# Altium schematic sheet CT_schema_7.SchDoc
size 278 x 170 mm
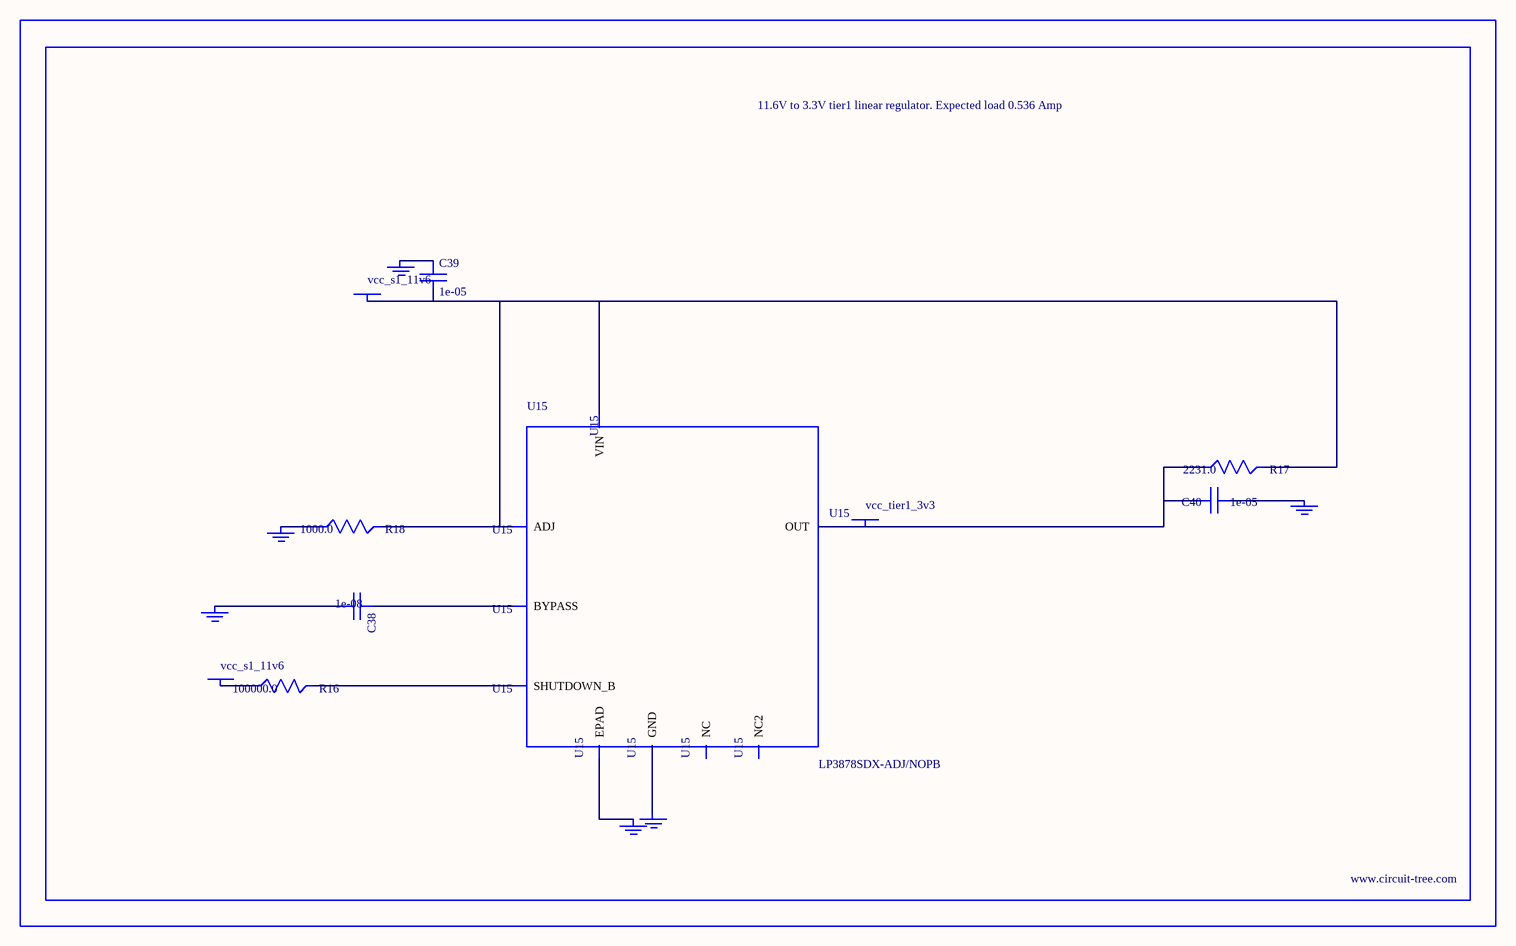
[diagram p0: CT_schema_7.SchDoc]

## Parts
BORDER6  (no value)
C38  1e-08  [C0402]
C39  1e-05  [C1210]
C40  1e-05  [C1210]
GND_INSTANCE_6_0  (no value)
GND_INSTANCE_6_1  (no value)
GND_INSTANCE_6_2  (no value)
GND_INSTANCE_6_3  (no value)
GND_INSTANCE_6_4  (no value)
GND_INSTANCE_6_5  (no value)
POWER_INSTANCE_6_0  vcc_s1_11v6
POWER_INSTANCE_6_1  vcc_s1_11v6
POWER_INSTANCE_6_2  vcc_tier1_3v3
R16  100000.0  [R0603]
R17  2231.0  [R0603]
R18  1000.0  [R0603]
U15  LP3878SDX-ADJ/NOPB  [WSON-8]

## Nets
NetC38_1: C38.1 U15.1(BYPASS)
NetC38_2: C38.2 GND_INSTANCE_6_0.0(GND)
NetC39_1: C39.1 GND_INSTANCE_6_1.0(GND)
NetC39_2: C39.2 POWER_INSTANCE_6_0.0(PWR) R17.2 R18.2 U15.4(VIN) U15.6(ADJ)
NetC40_1: C40.1 GND_INSTANCE_6_2.0(GND)
NetC40_2: C40.2 POWER_INSTANCE_6_2.0(PWR) R17.1 U15.5(OUT)
NetGND_INSTANCE_6_3_0: GND_INSTANCE_6_3.0(GND) R18.1
NetGND_INSTANCE_6_4_0: GND_INSTANCE_6_4.0(GND) U15.PAD(EPAD)
NetGND_INSTANCE_6_5_0: GND_INSTANCE_6_5.0(GND) U15.3(GND)
NetPOWER_INSTANCE_6_1_0: POWER_INSTANCE_6_1.0(PWR) R16.1
NetR16_2: R16.2 U15.8(SHUTDOWN_B)

Not connected (* = marked no-connect by the designer): U15 2(NC) 7(NC2)

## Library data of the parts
BORDER6 = BORDER_PAGE6
C38 = C0402C103K3RAC
C39 = C1210C106K5PACTU
C40 = GRM32DR61E106MA12L
GND_INSTANCE_6_0-GND_INSTANCE_6_5 = GND
POWER_INSTANCE_6_0-POWER_INSTANCE_6_2 = PWR
R16 = RC0603JR-07100KL
R17 = R17
R18 = RC0603JR-071KL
